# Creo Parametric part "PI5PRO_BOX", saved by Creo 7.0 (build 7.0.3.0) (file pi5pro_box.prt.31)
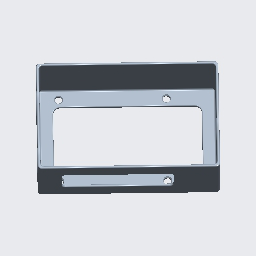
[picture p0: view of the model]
Units: millimeter Kilogram Sec (mmKs); MM, KILOGRAM, SECS

Created from: XX_SOLID_PART_MMKS_ABS.PRT

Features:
  1. coordinate system
  2. datum plane "RIGHT"
  3. datum plane "TOP"
  4. datum plane "FRONT"
  5. extrusion "Extrude 1"
  6. extrusion "Extrude 2"
  7. extruded cut "Extrude 3"
  8. extruded cut "Extrude 4"
  9. extruded cut "Extrude 5"
  10. extruded cut "Extrude 6"
  11. round "Round 1"
  12. round "Round 2"
  13. round "Round 3"
  14. round "Round 4"
  15. round "Round 6"
  16. chamfer "Chamfer 1"
  17. extruded cut "Extrude 7"
  18. round "Round 7"
  19. round "Round 8"
  20. round "Round 9"
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
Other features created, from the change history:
  round "Round 1"
  round "Round 5"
